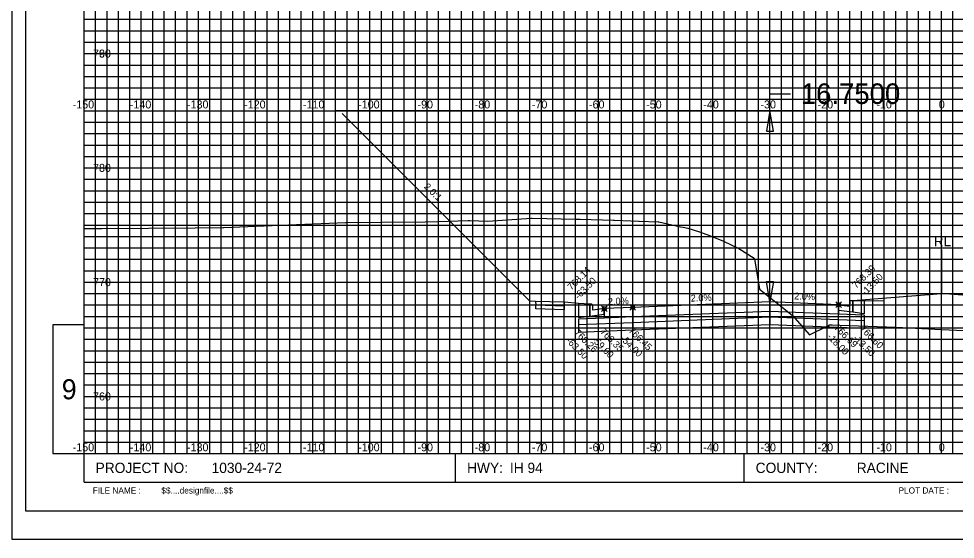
# Model space of a CAD drawing. Extents: x 578243 to 601557, y 174899 to 175559.
# Drawn here: x 600198.4 to 600362.3, y 174898.8 to 174989.9 of the extents above; entities that cross this region are included whole.
import ezdxf

# ---------------------------------------------------------------- set-up
doc = ezdxf.new("R2010")
doc.units = 0
for name, color, linetype in [('E_PROF_Grid', 7, 'Continuous'), ('E_PROF_GridMin', 7, 'Continuous'), ('P_CRDR_Label', 7, 'Continuous'), ('P_CRDR_Link', 7, 'Continuous'), ('P_E_XS_Ground', 7, 'Continuous'), ('P_RW_SlopeIntercepts', 7, 'Continuous'), ('P_XS_Text', 7, 'Continuous'), ('PLT_Sheet_Border', 7, 'Continuous'), ('PLT_Sheet_Info', 7, 'Continuous')]:
    doc.layers.add(name, color=color, linetype=linetype)

msp = doc.modelspace()

# ---------------------------------------------------------------- linework, layer by layer
at = {"layer": 'E_PROF_Grid'}
for p, q in [((600219.84, 174913.8), (600219.84, 175108.8)), ((600229.84, 174913.8), (600229.84, 175108.8)), ((600239.84, 174913.8), (600239.84, 175108.8)), ((600249.84, 174913.8), (600249.84, 175108.8)), ((600259.84, 174913.8), (600259.84, 175108.8)), ((600269.84, 174913.8), (600269.84, 175108.8)), ((600279.84, 174913.8), (600279.84, 175108.8)), ((600289.84, 174913.8), (600289.84, 175108.8)), ((600299.84, 174913.8), (600299.84, 175108.8)), ((600309.84, 174913.8), (600309.84, 175108.8)), ((600319.84, 174913.8), (600319.84, 175108.8)), ((600329.84, 174913.8), (600329.84, 175108.8)), ((600339.84, 174913.8), (600339.84, 175108.8)), ((600349.84, 174913.8), (600349.84, 175108.8)), ((600359.84, 174913.8), (600359.84, 175108.8)), ((600209.84, 174983.8), (600524.84, 174983.8)), ((600209.84, 174973.8), (600524.84, 174973.8)), ((600209.84, 174963.8), (600524.84, 174963.8)), ((600209.84, 174953.8), (600524.84, 174953.8)), ((600209.84, 174943.8), (600524.84, 174943.8)), ((600209.84, 174933.8), (600524.84, 174933.8)), ((600209.84, 174923.8), (600524.84, 174923.8))]:
    msp.add_line(p, q, dxfattribs=at)
at = {"layer": 'E_PROF_GridMin'}
for p, q in [((600211.84, 174913.8), (600211.84, 175108.8)), ((600213.84, 174913.8), (600213.84, 175108.8)), ((600215.84, 174913.8), (600215.84, 175108.8)), ((600217.84, 174913.8), (600217.84, 175108.8)), ((600221.84, 174913.8), (600221.84, 175108.8)), ((600223.84, 174913.8), (600223.84, 175108.8)), ((600225.84, 174913.8), (600225.84, 175108.8)), ((600227.84, 174913.8), (600227.84, 175108.8)), ((600231.84, 174913.8), (600231.84, 175108.8)), ((600233.84, 174913.8), (600233.84, 175108.8)), ((600235.84, 174913.8), (600235.84, 175108.8)), ((600237.84, 174913.8), (600237.84, 175108.8)), ((600241.84, 174913.8), (600241.84, 175108.8)), ((600243.84, 174913.8), (600243.84, 175108.8)), ((600245.84, 174913.8), (600245.84, 175108.8)), ((600247.84, 174913.8), (600247.84, 175108.8)), ((600251.84, 174913.8), (600251.84, 175108.8)), ((600253.84, 174913.8), (600253.84, 175108.8)), ((600255.84, 174913.8), (600255.84, 175108.8)), ((600257.84, 174913.8), (600257.84, 175108.8)), ((600261.84, 174913.8), (600261.84, 175108.8)), ((600263.84, 174913.8), (600263.84, 175108.8)), ((600265.84, 174913.8), (600265.84, 175108.8)), ((600267.84, 174913.8), (600267.84, 175108.8)), ((600271.84, 174913.8), (600271.84, 175108.8)), ((600273.84, 174913.8), (600273.84, 175108.8)), ((600275.84, 174913.8), (600275.84, 175108.8)), ((600277.84, 174913.8), (600277.84, 175108.8)), ((600281.84, 174913.8), (600281.84, 175108.8)), ((600283.84, 174913.8), (600283.84, 175108.8)), ((600285.84, 174913.8), (600285.84, 175108.8)), ((600287.84, 174913.8), (600287.84, 175108.8)), ((600291.84, 174913.8), (600291.84, 175108.8)), ((600293.84, 174913.8), (600293.84, 175108.8)), ((600295.84, 174913.8), (600295.84, 175108.8)), ((600297.84, 174913.8), (600297.84, 175108.8)), ((600301.84, 174913.8), (600301.84, 175108.8)), ((600303.84, 174913.8), (600303.84, 175108.8)), ((600305.84, 174913.8), (600305.84, 175108.8)), ((600307.84, 174913.8), (600307.84, 175108.8)), ((600311.84, 174913.8), (600311.84, 175108.8)), ((600313.84, 174913.8), (600313.84, 175108.8)), ((600315.84, 174913.8), (600315.84, 175108.8)), ((600317.84, 174913.8), (600317.84, 175108.8)), ((600321.84, 174913.8), (600321.84, 175108.8)), ((600323.84, 174913.8), (600323.84, 175108.8)), ((600325.84, 174913.8), (600325.84, 175108.8)), ((600327.84, 174913.8), (600327.84, 175108.8)), ((600331.84, 174913.8), (600331.84, 175108.8)), ((600333.84, 174913.8), (600333.84, 175108.8)), ((600335.84, 174913.8), (600335.84, 175108.8)), ((600337.84, 174913.8), (600337.84, 175108.8)), ((600341.84, 174913.8), (600341.84, 175108.8)), ((600343.84, 174913.8), (600343.84, 175108.8)), ((600345.84, 174913.8), (600345.84, 175108.8)), ((600347.84, 174913.8), (600347.84, 175108.8)), ((600351.84, 174913.8), (600351.84, 175108.8)), ((600353.84, 174913.8), (600353.84, 175108.8)), ((600355.84, 174913.8), (600355.84, 175108.8)), ((600357.84, 174913.8), (600357.84, 175108.8)), ((600361.84, 174913.8), (600361.84, 175108.8)), ((600209.84, 174989.8), (600524.84, 174989.8)), ((600209.84, 174987.8), (600524.84, 174987.8)), ((600209.84, 174985.8), (600524.84, 174985.8)), ((600209.84, 174981.8), (600524.84, 174981.8)), ((600209.84, 174979.8), (600524.84, 174979.8)), ((600209.84, 174977.8), (600524.84, 174977.8)), ((600209.84, 174975.8), (600524.84, 174975.8)), ((600209.84, 174971.8), (600524.84, 174971.8)), ((600209.84, 174969.8), (600524.84, 174969.8)), ((600209.84, 174967.8), (600524.84, 174967.8)), ((600209.84, 174965.8), (600524.84, 174965.8)), ((600209.84, 174961.8), (600524.84, 174961.8)), ((600209.84, 174959.8), (600524.84, 174959.8)), ((600209.84, 174957.8), (600524.84, 174957.8)), ((600209.84, 174955.8), (600524.84, 174955.8)), ((600209.84, 174951.8), (600524.84, 174951.8)), ((600209.84, 174949.8), (600524.84, 174949.8)), ((600209.84, 174947.8), (600524.84, 174947.8)), ((600209.84, 174945.8), (600524.84, 174945.8)), ((600209.84, 174941.8), (600524.84, 174941.8)), ((600209.84, 174939.8), (600524.84, 174939.8)), ((600209.84, 174937.8), (600524.84, 174937.8)), ((600209.84, 174935.8), (600524.84, 174935.8)), ((600209.84, 174931.8), (600524.84, 174931.8)), ((600209.84, 174929.8), (600524.84, 174929.8)), ((600209.84, 174927.8), (600524.84, 174927.8)), ((600209.84, 174925.8), (600524.84, 174925.8)), ((600209.84, 174921.8), (600524.84, 174921.8)), ((600209.84, 174919.8), (600524.84, 174919.8)), ((600209.84, 174917.8), (600524.84, 174917.8)), ((600209.84, 174915.8), (600524.84, 174915.8))]:
    msp.add_line(p, q, dxfattribs=at)
at = {"layer": 'P_CRDR_Label'}
for points in [[(600359.84, 174949.46), (600359.84, 174941.84)], [(600300.35, 174938.67), (600301.34, 174939.66)], [(600300.35, 174939.66), (600301.34, 174938.67)], [(600305.35, 174938.87), (600306.34, 174939.86)], [(600305.35, 174939.86), (600306.34, 174938.87)], [(600341.35, 174939.35), (600342.34, 174940.34)], [(600341.35, 174940.34), (600342.34, 174939.35)]]:
    msp.add_lwpolyline(points, dxfattribs=at)
for centre in [(600300.84, 174939.17), (600305.84, 174939.37), (600341.84, 174939.85)]:
    msp.add_circle(centre, 0.35, dxfattribs=at)
at = {"layer": 'P_CRDR_Link'}
msp.add_line((600254.99, 174973.31), (600287.84, 174940.46), dxfattribs=at)
for points in [[(600344.34, 174940.6), (600359.84, 174941.84)], [(600344.34, 174940.6), (600359.84, 174941.84)], [(600375.34, 174940.6), (600359.84, 174941.84)], [(600375.34, 174940.6), (600359.84, 174941.84)], [(600288.84, 174940.43), (600287.84, 174940.46)], [(600288.84, 174940.43), (600287.84, 174940.46)], [(600293.84, 174940.28), (600288.84, 174940.43)], [(600293.84, 174940.28), (600288.84, 174940.43)], [(600288.84, 174940.43), (600288.85, 174939.76)], [(600293.84, 174939.61), (600288.85, 174939.76)], [(600288.85, 174939.1), (600288.85, 174939.76)], [(600293.84, 174939.61), (600293.83, 174938.95)], [(600296.34, 174940.08), (600293.84, 174940.28)], [(600296.34, 174940.08), (600293.84, 174940.28)], [(600293.84, 174940.28), (600293.84, 174939.61)], [(600298.34, 174939.92), (600296.34, 174940.08)], [(600296.34, 174940.08), (600296.34, 174937.6)], [(600296.34, 174940.08), (600296.34, 174937.6)], [(600296.34, 174940.08), (600296.34, 174937.6)], [(600298.66, 174939.92), (600298.34, 174939.92)], [(600298.66, 174939.92), (600298.34, 174939.92)], [(600298.34, 174939.92), (600298.34, 174937.85)], [(600298.34, 174937.85), (600298.34, 174939.92)], [(600298.74, 174939.87), (600298.66, 174939.92)], [(600298.74, 174939.87), (600298.66, 174939.92)], [(600298.8, 174939.76), (600298.74, 174939.87)], [(600298.8, 174939.76), (600298.74, 174939.87)], [(600298.83, 174939.6), (600298.8, 174939.76)], [(600298.83, 174939.6), (600298.8, 174939.76)], [(600298.84, 174938.92), (600298.83, 174939.6)], [(600298.84, 174938.92), (600298.83, 174939.6)], [(600300.84, 174939.17), (600298.84, 174938.92)], [(600300.84, 174939.17), (600298.84, 174938.92)], [(600305.84, 174939.37), (600300.84, 174939.17)], [(600300.84, 174939.17), (600300.84, 174937.5)], [(600300.84, 174938.17), (600300.84, 174939.17)], [(600329.84, 174940.33), (600305.84, 174939.37)], [(600305.84, 174939.37), (600305.84, 174937.7)], [(600305.84, 174939.37), (600305.84, 174937.7)], [(600341.84, 174939.85), (600329.84, 174940.33)], [(600329.84, 174940.33), (600329.84, 174938.66)], [(600329.84, 174940.33), (600329.84, 174938.66)], [(600341.84, 174939.85), (600343.84, 174939.6)], [(600341.84, 174939.85), (600343.84, 174939.6)], [(600341.84, 174938.85), (600341.84, 174939.85)], [(600341.84, 174939.85), (600341.84, 174938.18)], [(600343.84, 174939.6), (600343.85, 174940.28)], [(600343.84, 174939.6), (600343.85, 174940.28)], [(600343.85, 174940.28), (600343.88, 174940.44)], [(600343.85, 174940.28), (600343.88, 174940.44)], [(600343.88, 174940.44), (600343.94, 174940.55)], [(600343.88, 174940.44), (600343.94, 174940.55)], [(600343.94, 174940.55), (600344.02, 174940.6)], [(600343.94, 174940.55), (600344.02, 174940.6)], [(600344.02, 174940.6), (600344.34, 174940.6)], [(600344.02, 174940.6), (600344.34, 174940.6)], [(600344.34, 174940.6), (600344.34, 174938.53)], [(600344.34, 174940.6), (600346.34, 174940.58)], [(600344.34, 174938.53), (600344.34, 174940.6)], [(600346.34, 174940.58), (600346.34, 174938.28)], [(600346.34, 174940.58), (600346.34, 174938.28)], [(600346.34, 174940.58), (600346.34, 174938.28)], [(600346.34, 174940.58), (600349.84, 174940.55)], [(600346.34, 174940.58), (600349.84, 174940.55)], [(600293.83, 174938.95), (600288.85, 174939.1)], [(600296.34, 174937.6), (600298.34, 174937.85)], [(600298.34, 174937.85), (600300.84, 174938.17)], [(600298.34, 174937.85), (600300.84, 174938.17)], [(600305.84, 174937.7), (600300.84, 174937.5)], [(600329.84, 174938.66), (600305.84, 174937.7)], [(600305.84, 174937.7), (600305.84, 174936.7)], [(600305.84, 174937.7), (600305.84, 174936.7)], [(600329.84, 174937.66), (600305.84, 174936.7)], [(600341.84, 174938.18), (600329.84, 174938.66)], [(600329.84, 174938.66), (600329.84, 174937.66)], [(600329.84, 174938.66), (600329.84, 174937.66)], [(600346.34, 174937), (600329.84, 174937.66)], [(600329.84, 174937.66), (600329.84, 174936.33)], [(600329.84, 174937.66), (600329.84, 174936.33)], [(600344.34, 174938.53), (600341.84, 174938.85)], [(600344.34, 174938.53), (600341.84, 174938.85)], [(600346.34, 174938), (600341.84, 174938.18)], [(600346.34, 174938.28), (600344.34, 174938.53)], [(600346.34, 174938), (600346.34, 174937)], [(600300.84, 174937.5), (600296.34, 174937.32)], [(600296.34, 174937.32), (600296.34, 174936.32)], [(600305.84, 174936.7), (600296.34, 174936.32)], [(600296.34, 174936.32), (600296.34, 174934.99)], [(600305.84, 174936.7), (600305.84, 174935.37)], [(600305.84, 174936.7), (600305.84, 174935.37)], [(600329.84, 174936.33), (600305.84, 174935.37)], [(600346.34, 174935.67), (600329.84, 174936.33)], [(600346.34, 174937), (600346.34, 174935.67)], [(600305.84, 174935.37), (600296.34, 174934.99)]]:
    msp.add_lwpolyline(points, dxfattribs=at)
at = {"layer": 'P_E_XS_Ground'}
msp.add_lwpolyline([(600209.84, 174953.19), (600212.24, 174953.17), (600212.92, 174953.17), (600229.29, 174953.31), (600234.14, 174953.35), (600234.27, 174953.35), (600244.14, 174953.76), (600255.54, 174954.22), (600255.74, 174954.23), (600261.82, 174954.28), (600269.53, 174954.33), (600271.79, 174954.42), (600277.03, 174954.6), (600277.3, 174954.6), (600280.45, 174954.49), (600280.49, 174954.49), (600288.05, 174954.99), (600288.25, 174955.02), (600295.87, 174954.85), (600296.66, 174954.84), (600302.44, 174954.63), (600302.62, 174954.62), (600305.52, 174954.52), (600306.91, 174954.46), (600306.93, 174954.46), (600310.27, 174954.34), (600310.41, 174954.33), (600314.16, 174953.49), (600314.64, 174953.44), (600315.48, 174953.27), (600317.5, 174952.58), (600319.24, 174951.95), (600321.69, 174950.96), (600324.39, 174949.7), (600327.05, 174948.02), (600327.13, 174947.85), (600328.02, 174942.57), (600333.7, 174938.02), (600336.78, 174934.6), (600339.94, 174936.18), (600340.25, 174936.33), (600340.71, 174936.32), (600342.08, 174936.26), (600351.86, 174935.94), (600359.84, 174935.54), (600367.8, 174935.14)], dxfattribs=at)
at = {"layer": 'P_RW_SlopeIntercepts'}
for p, q in [((600329.84, 174976.75), (600333.44, 174976.75)), ((600329.84, 174940.33), (600329.84, 174976.75)), ((600253.84, 174973.83), (600489.84, 174973.83)), ((600329.84, 174973.83), (600329.24, 174970.23)), ((600330.44, 174970.23), (600329.84, 174973.83)), ((600329.24, 174970.23), (600330.44, 174970.23)), ((600329.24, 174943.93), (600330.44, 174943.93)), ((600329.84, 174940.33), (600329.24, 174943.93)), ((600330.44, 174943.93), (600329.84, 174940.33))]:
    msp.add_line(p, q, dxfattribs=at)
at = {"layer": 'PLT_Sheet_Border'}
for points in [[(600197.19, 174898.8), (600537.19, 174898.8), (600537.19, 175118.8), (600197.19, 175118.8)], [(600199.59, 174903.8), (600530.59, 174903.8), (600530.59, 175113.8), (600199.59, 175113.8)]]:
    msp.add_lwpolyline(points, close=True, dxfattribs=at)
at = {"layer": 'PLT_Sheet_Info'}
for p, q in [((600209.84, 174908.8), (600209.84, 175108.8)), ((600209.84, 174913.8), (600524.84, 174913.8)), ((600274.84, 174908.8), (600274.84, 174913.8)), ((600325.34, 174908.8), (600325.34, 174913.8)), ((600209.84, 174908.8), (600524.84, 174908.8)), ((600197.19, 174898.8), (600207.19, 174898.8))]:
    msp.add_line(p, q, dxfattribs=at)
msp.add_lwpolyline([(600209.84, 174936.3), (600204.34, 174936.3), (600204.34, 174913.8), (600209.84, 174913.8)], close=True, dxfattribs=at)

# ---------------------------------------------------------------- texts
at = {"layer": 'P_CRDR_Label'}
for s, rotation, p in [('2.0:1', 315.8532, (600269.19, 174960.39)), ('768.14', 45, (600295.1, 174942.3)), ('768.39', 45, (600344.93, 174942.62)), ('-63.50', 45, (600296.34, 174940.71)), ('-13.50', 45, (600346.52, 174941.39)), ('2.0%', 2.2906, (600301.5, 174939.81)), ('2.0%', 2.2906, (600316, 174940.39)), ('2.0%', 357.7094, (600334.05, 174940.78)), ('766.45', 315, (600305.02, 174935.19)), ('766.69', 315, (600340.99, 174935.7)), ('766.60', 315, (600345.49, 174935.52)), ('766.26', 315, (600295.49, 174934.84)), ('766.35', 315, (600300.03, 174934.99)), ('-18.00', 315, (600339.73, 174934.14)), ('-63.50', 315, (600294.08, 174933.43)), ('-59.00', 315, (600298.58, 174933.61)), ('-54.00', 315, (600303.58, 174933.81)), ('-13.50', 315, (600344.29, 174933.9))]:
    msp.add_text(s, height=1.2, rotation=rotation, dxfattribs=at).set_placement(p)
msp.add_text('RL', height=1.75, dxfattribs=at).set_placement((600358.52, 174950.09))
at = {"layer": 'P_RW_SlopeIntercepts'}
msp.add_text('16.7500', height=3.6, dxfattribs=at).set_placement((600335.24, 174974.98))
at = {"layer": 'P_XS_Text'}
for s, p in [('790', (600211.38, 174983.1)), ('760', (600211.4, 174983.1)), ('-150', (600207.84, 174974.2)), ('-140', (600217.84, 174974.2)), ('-130', (600227.84, 174974.2)), ('-120', (600237.84, 174974.2)), ('-110', (600248.13, 174974.2)), ('-100', (600257.79, 174974.2)), ('-90', (600268.17, 174974.2)), ('-80', (600278.18, 174974.2)), ('-70', (600288.18, 174974.2)), ('-60', (600298.18, 174974.2)), ('-50', (600308.18, 174974.2)), ('-40', (600318.18, 174974.2)), ('-30', (600328.18, 174974.2)), ('-20', (600338.18, 174974.2)), ('-10', (600348.47, 174974.2)), ('0', (600359.39, 174974.2)), ('0', (600359.39, 174974.2)), ('780', (600211.4, 174963.1)), ('770', (600211.4, 174943.1)), ('760', (600211.4, 174923.1)), ('-150', (600207.84, 174914.2)), ('-140', (600217.84, 174914.2)), ('-130', (600227.84, 174914.2)), ('-120', (600237.84, 174914.2)), ('-110', (600248.13, 174914.2)), ('-100', (600257.79, 174914.2)), ('-90', (600268.17, 174914.2)), ('-80', (600278.18, 174914.2)), ('-70', (600288.18, 174914.2)), ('-60', (600298.18, 174914.2)), ('-50', (600308.18, 174914.2)), ('-40', (600318.18, 174914.2)), ('-30', (600328.18, 174914.2)), ('-20', (600338.18, 174914.2)), ('-10', (600348.47, 174914.2)), ('0', (600359.39, 174914.2)), ('0', (600359.39, 174914.2))]:
    msp.add_text(s, height=1.4, rotation=360, dxfattribs=at).set_placement(p)
at = {"layer": 'PLT_Sheet_Info'}
for s, height, p in [('9', 3.5, (600205.92, 174923.3)), ('PROJECT NO:', 1.8, (600211.84, 174910.4)), ('1030-24-72             ', 1.8, (600232.14, 174910.4)), ('HWY:', 1.8, (600276.84, 174910.4)), ('IH 94               ', 1.8, (600284.34, 174910.4)), ('COUNTY:', 1.8, (600327.34, 174910.4)), ('       RACINE       ', 1.8, (600340.34, 174910.4)), ('FILE NAME :', 1.08, (600211.34, 174906.8))]:
    msp.add_text(s, height=height, dxfattribs=at).set_placement(p)
for s, p in [('$$....designfile....$$', (600223.34, 174906.8)), ('PLOT DATE :', (600352.34, 174906.8))]:
    msp.add_text(s, height=1.08, rotation=360, dxfattribs=at).set_placement(p)

doc.saveas('drawing.dxf')
